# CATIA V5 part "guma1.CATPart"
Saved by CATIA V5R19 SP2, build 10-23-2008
Part number: guma
Bounding box of the stored display mesh (mm): x -39.99 to 39.99, y -34 to 34, z -39.957 to 39.957
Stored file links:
  D:\Catia fórum\Modely - Otazky\Naklapeni_oprava\guma1.CATPart
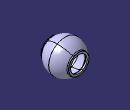
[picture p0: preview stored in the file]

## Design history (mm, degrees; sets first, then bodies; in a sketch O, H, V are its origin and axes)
Body1 (main body)
  Sketch1 on yz-plane, origin (0, 0, 0), H (0, 1, 0), V (0, 0, 1)
    axis line L1 (-72.232, 0) -> (45.0362, 0)
    point P1 (-72.232, 0)
    construction line L2 (0, 70.0582) -> (0, -36.1683)
    point P3 (0, 70.0582)
    line L3 (-34, 20) -> (-30.249, 20)
    line L4 (-34, 24.5) -> (-33.0568, 24.5)
    point P5 (-34.641, 20)
    point P6 (-28.7228, 20)
    line L5 (-34, 24.5) -> (-34, 20)
    arc A1 centre (-30.249, 23) radius 3 from (-27.8609, 21.1842) to (-30.249, 20) cw
    point P7 (-27.8609, 21.1842)
    point P8 (-30.249, 20)
    arc A2 centre (-33.0568, 27.5) radius 3 from (-30.7505, 25.5814) to (-33.0568, 24.5) cw
    point P10 (-30.7505, 25.5814)
    point P11 (-33.0568, 24.5)
    point P13 (-34, 24.5)
    point P14 (-34, 20)
    arc A3 centre (0, 0) radius 35 from (0, 35) to (-27.8609, 21.1842) ccw
    point P15 (0, 35)
    arc A4 centre (0, 0) radius 40 from (0, 40) to (-30.7505, 25.5814) ccw
    point P16 (0, 40)
    point P17 (34.641, 20)
    point P18 (28.7228, 20)
    point P19 (27.8609, 21.1842)
    point P20 (30.249, 20)
    point P22 (30.7505, 25.5814)
    point P23 (33.0568, 24.5)
    point P25 (34, 24.5)
    point P26 (34, 20)
    line L6 (34, 20) -> (30.249, 20)
    line L7 (34, 24.5) -> (33.0568, 24.5)
    line L8 (34, 24.5) -> (34, 20)
    arc A5 centre (30.249, 23) radius 3 from (27.8609, 21.1842) to (30.249, 20) ccw
    arc A6 centre (33.0568, 27.5) radius 3 from (30.7505, 25.5814) to (33.0568, 24.5) ccw
    point P27 (0, 40)
    arc A7 centre (0, 0) radius 40 from (0, 40) to (30.7505, 25.5814) cw
    point P29 (0, 35)
    arc A8 centre (0, 0) radius 35 from (0, 35) to (27.8609, 21.1842) cw
    distance L3 L1 = 20
    distance L4 L1 = 24.5
    distance L5 L2 = 34
    radius A1 = 3
    radius A2 = 3
    radius A3 = 35
    radius A4 = 40
    coincidence: P1 H, P3 V, L3 P5, L3 P6, L2 P15, L2 P16, P15 P29, P16 P27
    horizontal: L1 H, L3 H, L4 H
    vertical: L2 V, L5 V
    tangency: A1 L3, A2 L4
    symmetry: P5 P17 L2, P6 P18 L2, P7 P19 L2, P8 P20 L2, P10 P22 L2, P11 P23 L2, P13 P25 L2, P14 P26 L2, L3 L6 L2, L4 L7 L2, L5 L8 L2, A1 A5 L2, A2 A6 L2, P16 P27 L2, A4 A7 L2, P15 P29 L2, A3 A8 L2
  Shaft1: profile Sketch1, axis Sketch1.L1, angle 360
